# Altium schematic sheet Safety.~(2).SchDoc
size A
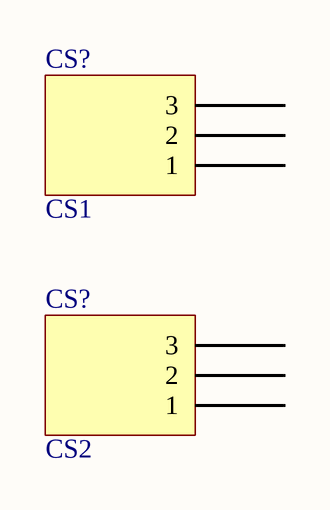
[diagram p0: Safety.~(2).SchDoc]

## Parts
(Parts that share a designator on the sheet are numbered #1, #2 ... from top to bottom, then left to right.)
CS?#1  CS1  [ACS712]
CS?#2  CS2  [ACS712]

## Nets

Not connected (* = marked no-connect by the designer): CS?#1 1 2 3; CS?#2 1 2 3

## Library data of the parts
CS?#1 CS?#2 = ACS712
